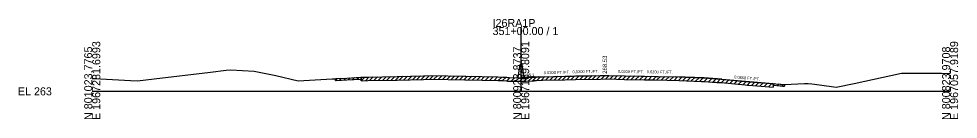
# Model space of a CAD drawing. Extents: x -26 to 304, y -10 to 7527.
# Drawn here: x -25.7 to 302.8, y 490.3 to 525.3 of the extents above; entities that cross this region are included whole.
import ezdxf

# ---------------------------------------------------------------- set-up
doc = ezdxf.new("R2010")
doc.units = 0
for name, color, linetype in [('RD_GPK_XS_Cell', 7, 'Continuous'), ('RD_XS_Base', 7, 'Continuous'), ('RD_XS_EarthShd', 7, 'Continuous'), ('RD_XS_ExGround', 7, 'Continuous'), ('RD_XS_ExPaveRet', 7, 'Continuous'), ('RD_XS_Misc_Line', 7, 'Continuous'), ('RD_XS_Pave', 7, 'Continuous'), ('RD_XS_PaveShd', 7, 'Continuous'), ('RD_XS_TX_Elev_EX', 7, 'Continuous'), ('RD_XS_TX_Elev_PR', 7, 'Continuous'), ('RD_XS_TX_MkPT', 7, 'Continuous'), ('RD_XS_TX_Profile', 7, 'Continuous'), ('RD_XS_TX_Station', 7, 'Continuous')]:
    doc.layers.add(name, color=color, linetype=linetype)

msp = doc.modelspace()

# ---------------------------------------------------------------- linework, layer by layer
at = {"layer": 'RD_GPK_XS_Cell'}
for p, q in [((150, 500), (150, 522.41)), ((0, 500), (150, 500)), ((150, 500), (300, 500))]:
    msp.add_line(p, q, dxfattribs=at)
at = {"layer": 'RD_XS_Base'}
msp.add_line((150, 504.77), (150, 504.81), dxfattribs=at)
at = {"layer": 'RD_XS_EarthShd'}
for p, q in [((149, 504.83), (149.67, 509.31)), ((150, 509.31), (149.67, 509.31)), ((150, 509.31), (150.33, 509.31)), ((151, 504.83), (150.33, 509.31))]:
    msp.add_line(p, q, dxfattribs=at)
at = {"layer": 'RD_XS_ExGround'}
msp.add_lwpolyline([(0, 504.42), (0.84, 504.44), (13.42, 503.8), (15.85, 503.67), (21.63, 504.38), (41.31, 506.67), (46.81, 507.32), (48.43, 507.47), (56.6, 507.07), (64.16, 505.49), (72, 503.68), (83.95, 504.34), (85.05, 504.39), (85.35, 504.44), (89.06, 504.64), (93.92, 504.91), (96.39, 504.97), (106.65, 505.18), (115.89, 505.4), (118.47, 505.46), (130.34, 505.29), (130.67, 505.28), (141.96, 505.02), (143.54, 504.97), (144.86, 504.93), (145.21, 504.83), (145.64, 504.81), (148.5, 504.75), (150, 504.77), (150.81, 504.78), (151.18, 504.79), (151.67, 504.8), (154.52, 504.89), (154.7, 504.97), (155.31, 504.99), (157.49, 505.09), (165.22, 505.29), (169, 505.39), (177.77, 505.51), (180.54, 505.55), (186.1, 505.43), (193.12, 505.3), (196.75, 505.21), (205.3, 505.01), (213.11, 504.73), (214.02, 504.69), (215.49, 504.59), (216.94, 504.5), (217.98, 504.42), (218.46, 504.38), (218.76, 504.35), (219.89, 504.29), (228.35, 503.46), (229.19, 503.37), (229.66, 503.34), (240.63, 502.54), (240.86, 502.48), (241.38, 502.38), (241.77, 502.38), (242.13, 502.38), (246.79, 502.59), (249.12, 502.68), (249.91, 502.71), (250.34, 502.73), (251.67, 502.56), (254.31, 502.23), (260.11, 501.44), (266.42, 502.74), (282.98, 506.32), (293.01, 506.32), (296.95, 506.35), (300, 506.18)], dxfattribs=at)
at = {"layer": 'RD_XS_ExPaveRet'}
for p, q in [((85.05, 503.77), (85.05, 504.39)), ((85.05, 503.77), (85.35, 503.81)), ((85.35, 503.81), (89.06, 504.02)), ((89.06, 504.02), (93.92, 504.29)), ((93.92, 504.29), (94, 504.29)), ((94, 503.67), (94, 504.92)), ((94, 504.92), (94, 504.29)), ((94, 503.67), (96.39, 503.72)), ((96.39, 503.72), (106.65, 503.93)), ((106.65, 503.93), (115.89, 504.15)), ((115.89, 504.15), (118.47, 504.21)), ((118.47, 504.21), (130.34, 504.04)), ((130.34, 504.04), (130.67, 504.03)), ((130.67, 504.03), (141.96, 503.77)), ((141.96, 503.77), (143.54, 503.72)), ((143.54, 503.72), (144.86, 503.68)), ((144.86, 503.68), (145.21, 503.58)), ((145.21, 503.58), (145.64, 503.56)), ((145.64, 503.56), (148.5, 503.5)), ((148.5, 503.5), (150, 503.52)), ((150, 503.52), (150.81, 503.53)), ((150.81, 503.53), (151.18, 503.54)), ((151.18, 503.54), (151.67, 503.55)), ((151.67, 503.55), (154.52, 503.64)), ((154.52, 503.64), (154.7, 503.72)), ((154.7, 503.72), (155.31, 503.74)), ((155.31, 503.74), (157.49, 503.84)), ((157.49, 503.84), (165.22, 504.04)), ((165.22, 504.04), (169, 504.14)), ((169, 504.14), (177.77, 504.26)), ((177.77, 504.26), (180.54, 504.3)), ((180.54, 504.3), (186.1, 504.18)), ((186.1, 504.18), (193.12, 504.05)), ((193.12, 504.05), (196.75, 503.96)), ((196.75, 503.96), (205.3, 503.76)), ((205.3, 503.76), (213.11, 503.48)), ((213.11, 503.48), (214.02, 503.44)), ((214.02, 503.44), (215.49, 503.34)), ((215.49, 503.34), (216.94, 503.25)), ((216.94, 503.25), (217.98, 503.17)), ((217.98, 503.17), (218.46, 503.13)), ((218.46, 503.13), (218.76, 503.1)), ((218.76, 503.1), (219.89, 503.04)), ((219.89, 503.04), (228.35, 502.21)), ((238.1, 502.72), (238.1, 501.47)), ((238.1, 502.1), (238.1, 502.72)), ((228.35, 502.21), (229.19, 502.12)), ((229.19, 502.12), (229.66, 502.09)), ((229.66, 502.09), (238.1, 501.47)), ((238.1, 502.1), (240.63, 501.91)), ((240.63, 501.91), (240.86, 501.86)), ((240.86, 501.86), (241.38, 501.76)), ((241.38, 501.76), (241.77, 501.76)), ((241.77, 501.76), (242.13, 501.76)), ((242.13, 502.38), (242.13, 501.76))]:
    msp.add_line(p, q, dxfattribs=at)
at = {"layer": 'RD_XS_Misc_Line'}
for p, q in [((85.05, 503.77), (85.74, 504.46)), ((86.55, 503.88), (87.21, 504.54)), ((88.05, 503.96), (88.71, 504.62)), ((89.55, 504.05), (90.21, 504.71)), ((91.05, 504.13), (91.72, 504.79)), ((92.56, 504.21), (93.22, 504.87)), ((94, 503.67), (95.28, 504.94)), ((95.5, 503.7), (96.78, 504.98)), ((97, 503.73), (98.28, 505.01)), ((98.5, 503.76), (99.78, 505.04)), ((100, 503.79), (101.28, 505.07)), ((101.5, 503.82), (102.78, 505.1)), ((103, 503.85), (104.28, 505.13)), ((104.5, 503.89), (105.78, 505.16)), ((106, 503.92), (107.28, 505.19)), ((107.5, 503.95), (108.78, 505.23)), ((109, 503.99), (110.28, 505.27)), ((110.5, 504.02), (111.78, 505.3)), ((112, 504.06), (113.28, 505.34)), ((113.5, 504.09), (114.78, 505.37)), ((115, 504.13), (116.28, 505.41)), ((116.5, 504.16), (117.78, 505.44)), ((118, 504.2), (119.25, 505.45)), ((119.5, 504.2), (120.73, 505.43)), ((121, 504.17), (122.23, 505.41)), ((122.5, 504.15), (123.73, 505.39)), ((124, 504.13), (125.23, 505.36)), ((125.5, 504.11), (126.73, 505.34)), ((127, 504.09), (128.23, 505.32)), ((128.5, 504.07), (129.73, 505.3)), ((130, 504.04), (131.23, 505.27)), ((131.5, 504.01), (132.72, 505.24)), ((133, 503.98), (134.22, 505.2)), ((134.5, 503.94), (135.72, 505.17)), ((136, 503.91), (137.22, 505.13)), ((137.5, 503.88), (138.72, 505.1)), ((139, 503.84), (140.22, 505.06)), ((140.5, 503.81), (141.72, 505.03)), ((142, 503.77), (143.21, 504.98)), ((143.5, 503.72), (144.71, 504.93)), ((145, 503.63), (146.17, 504.8)), ((146.5, 503.54), (147.72, 504.76)), ((148, 503.51), (149.25, 504.76)), ((149.5, 503.51), (150.77, 504.78)), ((151, 503.53), (152.29, 504.82)), ((152.5, 503.58), (153.79, 504.87)), ((154, 503.62), (155.37, 505)), ((155.5, 503.75), (156.8, 505.06)), ((157, 503.81), (158.29, 505.11)), ((158.5, 503.86), (159.78, 505.15)), ((160, 503.9), (161.28, 505.19)), ((161.5, 503.94), (162.78, 505.23)), ((163, 503.98), (164.28, 505.27)), ((164.5, 504.02), (165.78, 505.31)), ((166, 504.06), (167.28, 505.35)), ((167.5, 504.1), (168.78, 505.39)), ((169, 504.14), (170.27, 505.41)), ((170.5, 504.16), (171.77, 505.43)), ((172, 504.18), (173.27, 505.45)), ((173.5, 504.2), (174.77, 505.47)), ((175, 504.22), (176.27, 505.49)), ((176.5, 504.24), (177.77, 505.51)), ((178, 504.26), (179.27, 505.53)), ((179.5, 504.28), (180.76, 505.54)), ((181, 504.29), (182.23, 505.51)), ((182.5, 504.26), (183.73, 505.48)), ((184, 504.23), (185.23, 505.45)), ((185.5, 504.2), (186.73, 505.42)), ((187, 504.17), (188.23, 505.39)), ((188.5, 504.14), (189.73, 505.36)), ((190, 504.11), (191.23, 505.33)), ((191.5, 504.08), (192.73, 505.31)), ((193, 504.05), (194.22, 505.27)), ((194.5, 504.02), (195.72, 505.24)), ((196, 503.98), (197.22, 505.2)), ((197.5, 503.95), (198.72, 505.17)), ((199, 503.91), (200.22, 505.13)), ((200.5, 503.88), (201.72, 505.1)), ((202, 503.84), (203.22, 505.06)), ((203.5, 503.81), (204.72, 505.03)), ((205, 503.77), (206.21, 504.98)), ((206.5, 503.72), (207.71, 504.93)), ((208, 503.67), (209.21, 504.87)), ((209.5, 503.61), (210.71, 504.82)), ((211, 503.56), (212.21, 504.76)), ((212.5, 503.5), (213.7, 504.7)), ((214, 503.44), (215.17, 504.61)), ((215.5, 503.34), (216.67, 504.51)), ((217, 503.24), (218.16, 504.4)), ((218.5, 503.13), (219.67, 504.3)), ((220, 503.03), (221.14, 504.16)), ((221.5, 502.88), (222.64, 504.02)), ((223, 502.73), (224.14, 503.87)), ((224.5, 502.58), (225.64, 503.72)), ((226, 502.44), (227.14, 503.58)), ((227.5, 502.29), (228.64, 503.43)), ((229, 502.14), (230.16, 503.3)), ((230.5, 502.03), (231.66, 503.19)), ((232, 501.92), (233.16, 503.08)), ((233.5, 501.81), (234.66, 502.97)), ((235, 501.7), (236.16, 502.86)), ((236.5, 501.59), (237.66, 502.75)), ((238.1, 502.1), (238.68, 502.68)), ((239.6, 501.99), (240.18, 502.57)), ((241.1, 501.81), (241.68, 502.38))]:
    msp.add_line(p, q, dxfattribs=at)
at = {"layer": 'RD_XS_Pave'}
for p, q in [((156, 505.05), (180, 505.53)), ((180, 505.53), (204, 505.05)), ((220.12, 504.26), (238.1, 502.72))]:
    msp.add_line(p, q, dxfattribs=at)
at = {"layer": 'RD_XS_PaveShd'}
for p, q in [((156, 505.05), (150, 504.81)), ((214.02, 504.69), (204, 505.05)), ((220.12, 504.26), (214.02, 504.69))]:
    msp.add_line(p, q, dxfattribs=at)
at = {"layer": 'RD_XS_TX_Elev_PR'}
msp.add_lwpolyline([(150, 504.77), (150.81, 504.78), (151.18, 504.79), (151.67, 504.8), (154.52, 504.89), (154.7, 504.97), (155.31, 504.99), (157.49, 505.09), (165.22, 505.29), (169, 505.39), (177.77, 505.51), (180.54, 505.55), (186.1, 505.43), (193.12, 505.3), (196.75, 505.21), (205.3, 505.01), (213.11, 504.73), (214.02, 504.69), (215.49, 504.59), (216.94, 504.5), (217.98, 504.42), (218.46, 504.38), (218.76, 504.35), (219.89, 504.29), (228.35, 503.46), (229.19, 503.37), (229.66, 503.34), (238.1, 502.72)], dxfattribs=at)

# ---------------------------------------------------------------- texts
at = {"layer": 'RD_GPK_XS_Cell'}
for s, p in [('351+00.00 / 1', (140, 519.61)), ('I26RA1P', (140, 522.41)), ('EL 263', (-26, 498.6))]:
    msp.add_text(s, height=2.8, dxfattribs=at).set_placement(p)
for s, p in [('E 1967281.6993', (2.8, 490)), ('E 1967169.8091', (152.8, 490)), ('E 1967057.9189', (302.8, 490)), ('N 801023.7765', (0, 490)), ('N 800923.8737', (150, 490)), ('N 800823.9708', (300, 490))]:
    msp.add_text(s, height=2.8, rotation=90, dxfattribs=at).set_placement(p)
at = {"layer": 'RD_XS_TX_Elev_EX'}
msp.add_text('267.77', height=1, rotation=90, dxfattribs=at).set_placement((151, 504.77))
at = {"layer": 'RD_XS_TX_MkPT'}
msp.add_text('25:1', height=1, rotation=2.2906, dxfattribs=at).set_placement((151.94, 505.14))
at = {"layer": 'RD_XS_TX_Profile'}
for s, rotation, p in [('0.0200 FT./FT.', 1.1458, (157.92, 505.98)), ('0.0200 FT./FT.', 1.1458, (167.98, 506.29)), ('0.0200 FT./FT.', 358.8542, (183.83, 506.45)), ('0.0200 FT./FT.', 358.8542, (193.89, 506.33)), ('0.0858 FT./FT.', 355.0962, (224.45, 504.51))]:
    msp.add_text(s, height=1, rotation=rotation, dxfattribs=at).set_placement(p)
at = {"layer": 'RD_XS_TX_Station'}
msp.add_text(' 268.53', height=1.5, rotation=90, dxfattribs=at).set_placement((180, 505.53))

doc.saveas('drawing.dxf')
